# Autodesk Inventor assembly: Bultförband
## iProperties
Shininess: 64.0
Length Units: 11269
Angle Units: 11279
Time Units: 11290
Mass Units: 11283
Length Display Precision: 3
Angle Display Precision: 2
Compacted: True
Part Number: Bultförband
Document SubType Name: Assembly
Created: 2004-01
Designer: Administratör
Manufacturer: Standard
Standards Organization: Custom
Density: 0.0
Volumn: 0.0
Area: 0.0
PropertySet Name: Model Information
Control State: 0
Master: False
Checked Out: False
Author: Administratör
